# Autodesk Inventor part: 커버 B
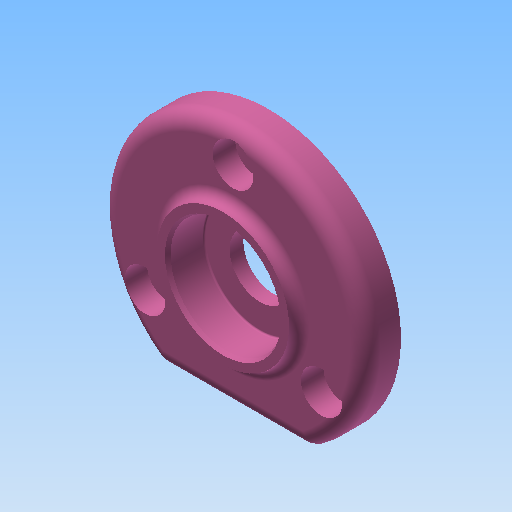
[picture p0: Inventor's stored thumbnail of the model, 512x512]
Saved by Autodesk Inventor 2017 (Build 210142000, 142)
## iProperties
Created: 2020-04
Part Number: 커버 B
Material: 알루미늄 6061
Document SubType Name: Modeling
Designer: mduedu
Density: 2.71 g/cm^3
Appearance: 분홍색
Mass: 33.6775 g
Surface Area: 62.2844 cm^2
Volume: 12.4271 cm^3
Author: mduedu
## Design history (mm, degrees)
sketch "스케치1"
  geometry: C1 r 26 at (0, 0); 1 further point
  constraints: 1 centre point, 1 coincident
  dimensions: "d0" = 52 diameter of C1
extrude "돌출1" new body sketch "스케치1" distance "d1" = 7; taper "d2" = 0 deg
sketch "스케치2"
  geometry: L1 (-14.62, -21.5)-(14.62, -21.5); A1 r 26 centre (0, 0) between (-14.62, -21.5) and (14.62, -21.5) reference; 1 further point
  constraints: 2 end point, 2 point on circle, 1 horizontal
  dimensions: "d3" = 21.5 distance from line of L1 point (0, 0)
extrude "돌출2" cut sketch "스케치2" stored distance "d4" = 7; taper "d5" = 0 deg
sketch "스케치6"
  geometry: C1 r 13 at (0, 0); 1 further point
  constraints: 1 centre point, 1 coincident
  dimensions: "d29" = 26 diameter of C1
extrude "돌출5" join sketch "스케치6" distance "d30" = 2; taper "d31" = 0 deg
fillet "모깎기1" dims "d6" = 3
fillet "모깎기2" dims "d7" = 3
fillet "모깎기4" dims "d33" = 2
sketch "스케치3" dims "d8" = 40
  geometry: 3 further points
  constraints: 2 vertical alignment, 1 coincident, 2 other
hole "구멍1" sketch "스케치3" at (0, 20) diameter "d9" = 4.5; stored, may be unused: countersink angle "d13" = 90 deg, drill point angle "d15" = 118 deg; dims "d10" = 6, "d11" = 8, "d12" = 4.4, "d14" = 8
sketch "스케치4"
  geometry: C1 r 14 at (0, 0); 1 further point
  constraints: 1 centre point, 1 coincident
  dimensions: "d19" = 28 diameter of C1
extrude "돌출3" join sketch "스케치4" distance "d20" = 4; taper "d21" = 0 deg
sketch "스케치5"
  geometry: C1 r 12 at (0, 0); 1 further point
  constraints: 1 centre point, 1 coincident
  dimensions: "d22" = 24 diameter of C1
extrude "돌출4" cut sketch "스케치5" distance "d23" = 3; taper "d24" = 0 deg
fillet "모깎기3" dims "d25" = 3
chamfer "모따기1" distance "d26" = 0.5; stored, may be unused: second distance "d27" = 2, angle "d28" = 45 deg
sketch "스케치7"
  geometry: 2 further points
  constraints: 1 coincident
hole "구멍2" sketch "스케치7" at (0, 0) diameter "d34" = 12; stored, may be unused: countersink angle "d38" = 90 deg, drill point angle "d40" = 118 deg; dims "d35" = 6, "d36" = 22, "d37" = 7.3, "d39" = 8
fillet "모깎기5" dims "d41" = 0.3
chamfer "모따기2" distance "d42" = 0.7; stored, may be unused: second distance "d43" = 2, angle "d44" = 30 deg
node "솔리드1"
pattern_circular "원형 패턴1" dims angle "d17" = 360 deg
node "투영된 루프1"
